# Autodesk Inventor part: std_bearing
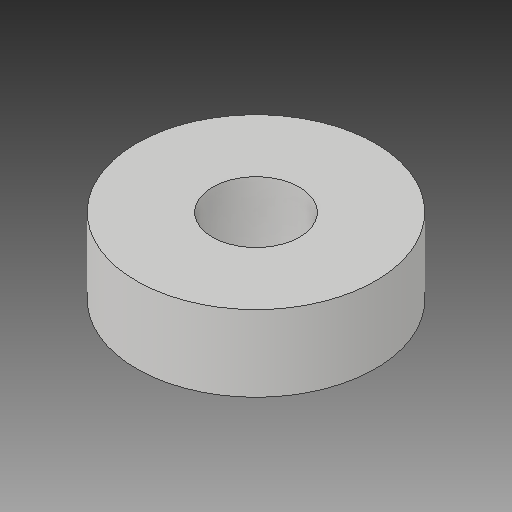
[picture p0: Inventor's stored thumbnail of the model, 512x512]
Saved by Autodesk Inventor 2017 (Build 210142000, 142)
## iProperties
Created: 2017-04
Part Number: std_bearing
Material: Generic
Document SubType Name: Modeling
Designer: s4321966
Density: 1 g/cm^3
Appearance: Default
Author: s4321966
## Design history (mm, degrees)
sketch "Sketch2"
  geometry: C1 r 4 at (0, 0); C2 r 11 at (0, 0); 1 further point
  constraints: 2 centre point, 2 coincident
  dimensions: "d21" = 8 diameter of C1; "d22" = 22 diameter of C2
extrude "Extrusion1" new body sketch "Sketch2" distance "d23" = 7; taper "d24" = 0 deg
body "Solid2"
